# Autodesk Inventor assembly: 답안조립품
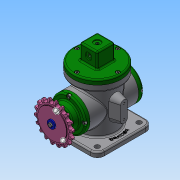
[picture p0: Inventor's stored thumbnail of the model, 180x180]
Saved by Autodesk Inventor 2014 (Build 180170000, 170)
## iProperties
Created: 2021-03
Part Number: 답안조립품
Document SubType Name: Assembly
Designer: net
Author: net
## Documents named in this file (19)
- C:\Users\net\Desktop\710306V1024\답안조립품.iam
- C:\Users\net\Desktop\710306V1024\본체.ipt
- C:\Users\net\Desktop\710306V1024\앞커버.ipt
- C:\Users\net\Desktop\710306V1024\오일 실 17 30 8.ipt
- C:\Users\net\Desktop\710306V1024\베어링 17 x 40 x 12.ipt
- C:\Users\net\Desktop\710306V1024\볼트 M4 x 10.ipt
- C:\Users\net\Desktop\710306V1024\뒤커버.ipt
- C:\Users\net\Desktop\710306V1024\편심축.ipt
- C:\Users\net\Desktop\710306V1024\키 4 x 4 x 12.ipt
- C:\Users\net\Desktop\710306V1024\와셔 4x16.ipt
- C:\Users\net\Desktop\710306V1024\스프로킷.ipt
- C:\Users\net\Desktop\710306V1024\볼트 M4 x 8.ipt
- C:\Users\net\Desktop\710306V1024\링크.ipt
- C:\Users\net\Desktop\710306V1024\멈춤나사 M3.ipt
- C:\Users\net\Desktop\710306V1024\클레비스 핀 6 x 22.ipt
- 클레비스 핀 6 x 22.ipt
- C:\Users\net\Desktop\710306V1024\E-링.ipt
- C:\Users\net\Desktop\710306V1024\슬라이더.ipt
- C:\Users\net\Desktop\710306V1024\덮개.ipt
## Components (1 placed, 1 different names)
1. E-링:1
